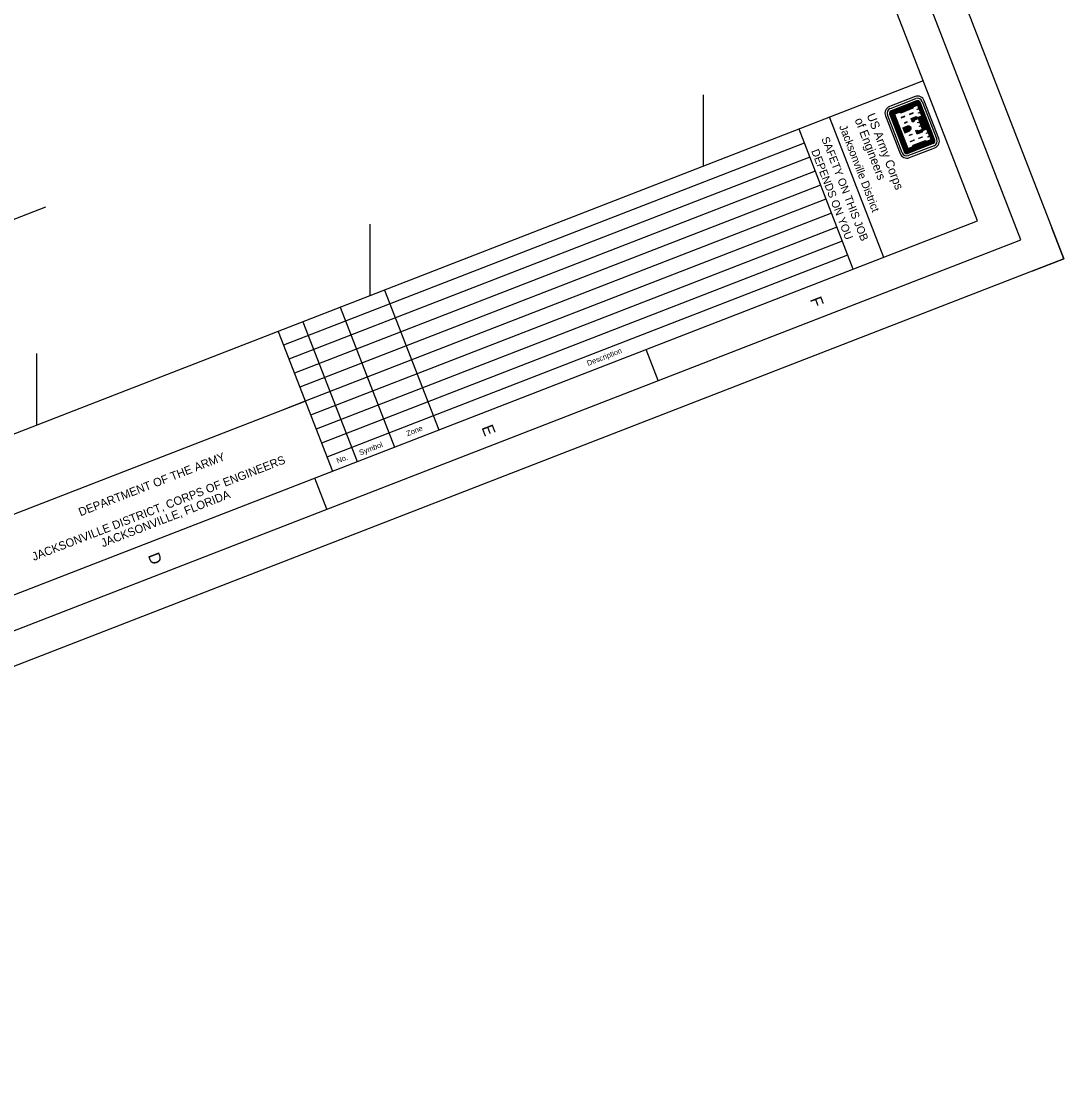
# Model space of a CAD drawing. Extents: x 587779 to 592541, y 824574 to 829906.
# Drawn here: x 590976 to 592541, y 824574 to 826161 of the extents above; entities that cross this region are included whole.
import ezdxf

# ---------------------------------------------------------------- set-up
doc = ezdxf.new("R2010")
doc.units = 0
for name, color, linetype in [('G-ANNO-NPLT', 7, 'Continuous'), ('G-ANNO-TEXT-LOGO', 7, 'Continuous'), ('G-ANNO-TEXT-TTLB', 7, 'Continuous'), ('G-ANNO-TTLB', 7, 'Continuous'), ('V-ANNO-MATC', 7, 'Continuous'), ('V-TOPO-COOR-STAT', 7, 'Continuous')]:
    doc.layers.add(name, color=color, linetype=linetype)

msp = doc.modelspace()

# ---------------------------------------------------------------- linework, layer by layer
at = {"layer": 'G-ANNO-NPLT'}
msp.add_lwpolyline([(590949.1, 829906.3), (592540.6, 825804.2), (589370.9, 824574.4), (587779.3, 828676.5)], close=True, dxfattribs=at)
msp.add_lwpolyline([(592494, 825786.1), (592540.6, 825804.2), (592522.5, 825850.8)], dxfattribs=at)
at = {"layer": 'G-ANNO-TEXT-LOGO'}
for p, q in [((592317.4, 826047.6), (592279.2, 826032.8)), ((592280.3, 826029.8), (592318.5, 826044.6)), ((592319.8, 826041.3), (592281.6, 826026.5)), ((592320.1, 826040.5), (592281.9, 826025.7)), ((592320.4, 826039.8), (592282.2, 826024.9)), ((592320.8, 826038.9), (592282.5, 826024.1)), ((592321.1, 826038.1), (592282.9, 826023.2)), ((592321.4, 826037.2), (592283.5, 826022.5)), ((592343.8, 825981.1), (592321.8, 826037.8)), ((592344.6, 825981.5), (592322.7, 826038.2)), ((592345.4, 825981.8), (592323.4, 826038.4)), ((592346.2, 825982.1), (592324.2, 826038.8)), ((592347.1, 825982.4), (592325.1, 826039.1)), ((592328.3, 826040.3), (592350.2, 825983.6)), ((592353.2, 825984.8), (592331.2, 826041.5)), ((592301.3, 825964.7), (592279.3, 826021.3)), ((592302, 825964.9), (592280.1, 826021.6)), ((592302.9, 825965.3), (592280.9, 826022)), ((592303.7, 825965.6), (592281.7, 826022.3)), ((592304.5, 825965.9), (592282.5, 826022.6)), ((592305.2, 825966.6), (592283.5, 826022.5)), ((592321.7, 826036.5), (592284.6, 826022.1)), ((592305.7, 825967.7), (592284.6, 826022.1)), ((592313.8, 826032.7), (592294.3, 826025.1)), ((592313.3, 826031.5), (592295.5, 826024.6)), ((592273, 826018.9), (592295, 825962.2)), ((592298, 825963.4), (592276, 826020.1)), ((592323.9, 826016), (592330.6, 825998.6)), ((592324.7, 826016.3), (592331.4, 825999)), ((592325.4, 826016.6), (592332.2, 825999.3)), ((592326.3, 826016.9), (592333, 825999.6)), ((592327.1, 826017.3), (592333.8, 825999.9)), ((592327.9, 826017.5), (592334.6, 826000.2)), ((592328.7, 826017.9), (592335.4, 826000.5)), ((592299.2, 826000.7), (592305.4, 826003.2)), ((592299.2, 826000.7), (592302.1, 825993.3)), ((592299.5, 826000), (592305.7, 826002.4)), ((592299.8, 825999.2), (592306.1, 826001.6)), ((592300.1, 825998.3), (592306.4, 826000.7)), ((592300.4, 825997.6), (592306.7, 826000)), ((592300.9, 825996.4), (592307.1, 825998.9)), ((592301.2, 825995.7), (592307.4, 825998.1)), ((592301.5, 825994.9), (592307.7, 825997.3)), ((592301.8, 825994), (592308.1, 825996.4)), ((592302.1, 825993.3), (592308.3, 825995.7)), ((592343.1, 825981.3), (592305.2, 825966.6)), ((592343.4, 825980.5), (592305.2, 825965.6)), ((592343.8, 825979.6), (592305.5, 825964.8)), ((592342.8, 825982), (592305.7, 825967.7)), ((592344, 825978.9), (592305.8, 825964)), ((592344.4, 825978), (592306.1, 825963.2)), ((592344.7, 825977.2), (592306.5, 825962.4)), ((592345.9, 825974), (592307.7, 825959.2)), ((592334.4, 825979.5), (592315, 825972)), ((592333.3, 825980.1), (592315.5, 825973.2)), ((592308.9, 825956.1), (592347.1, 825971))]:
    msp.add_line(p, q, dxfattribs=at)
for points in [[(592321.9, 826035.8), (592314.6, 826033), (592313.6, 826030.8), (592295.8, 826023.9), (592293.5, 826024.8), (592285.4, 826021.7), (592306, 825968.5), (592314.1, 825971.7), (592315.2, 825974), (592333, 825980.9), (592335.2, 825979.8), (592342.6, 825982.7), (592339.9, 825989.7), (592337.8, 825995.1), (592335.8, 826000.1), (592328.4, 825997.3), (592327.5, 825994.9), (592321, 825992.4), (592319.5, 825996.3), (592320.1, 825996.5), (592322.5, 825995.5), (592329.7, 825998.3), (592327, 826005.3), (592324.9, 826010.7), (592323, 826015.7), (592315.7, 826012.8), (592314.7, 826010.5), (592314.1, 826010.3), (592312.5, 826014.2), (592319.1, 826016.7), (592321.3, 826015.6), (592328.7, 826018.5), (592326, 826025.5), (592323.9, 826030.9), (592321.9, 826035.8)], [(592321.4, 826034.8), (592315.2, 826032.4), (592314.2, 826030.1), (592295.8, 826022.9), (592293.4, 826023.9), (592286.5, 826021.2), (592306.6, 825969.6), (592313.5, 825972.3), (592314.5, 825974.7), (592332.9, 825981.9), (592335.3, 825980.7), (592341.4, 825983.1), (592339.5, 825988.2), (592336.6, 825987), (592336.4, 825987.5), (592339.3, 825988.6), (592337.4, 825993.6), (592334.5, 825992.4), (592334.3, 825992.8), (592337.2, 825993.9), (592335.3, 825999), (592329.1, 825996.6), (592328.1, 825994.3), (592320.6, 825991.3), (592318.5, 825996.7), (592320.2, 825997.4), (592322.6, 825996.4), (592328.7, 825998.8), (592326.8, 826003.8), (592323.9, 826002.7), (592323.7, 826003.1), (592326.6, 826004.2), (592324.7, 826009.2), (592321.8, 826008.1), (592321.6, 826008.6), (592324.5, 826009.7), (592322.6, 826014.6), (592316.4, 826012.2), (592315.4, 826009.9), (592313.6, 826009.2), (592311.5, 826014.6), (592319.1, 826017.6), (592321.4, 826016.5), (592327.5, 826018.9), (592325.6, 826023.9), (592322.7, 826022.7), (592322.6, 826023.2), (592325.4, 826024.3), (592323.5, 826029.4), (592320.6, 826028.2), (592320.5, 826028.6), (592323.3, 826029.7), (592321.4, 826034.8)], [(592314.4, 826023.3), (592309, 826021.2), (592309.2, 826020.6), (592314.6, 826022.7), (592314.4, 826023.3)], [(592302, 826018.4), (592296.5, 826016.3), (592296.7, 826015.8), (592302.2, 826017.9), (592302, 826018.4)], [(592305.3, 826009.9), (592301.5, 826008.4), (592301.7, 826007.9), (592305.5, 826009.4), (592305.3, 826009.9)], [(592319.7, 826015.4), (592319, 826015.7), (592313.7, 826013.7), (592314.4, 826011.9), (592315.1, 826013.6), (592319.8, 826015.4)], [(592312.8, 825990.7), (592308.9, 825989.2), (592308.8, 825989.6), (592312.6, 825991.1), (592312.8, 825990.7)], [(592327.1, 825996.2), (592326.8, 825995.6), (592321.5, 825993.5), (592320.9, 825995.2), (592322.5, 825994.6), (592327.2, 825996.4)], [(592316.1, 825982.2), (592310.6, 825980), (592310.4, 825980.5), (592315.9, 825982.6), (592316.1, 825982.2)], [(592328.5, 825987), (592323, 825984.9), (592322.9, 825985.4), (592328.3, 825987.5), (592328.5, 825987)]]:
    msp.add_lwpolyline(points, dxfattribs=at)
for centre, major_axis, start_param, end_param in [((592321.3, 826037.6), (3.88, -9.99), 1.57078, 3.141576), ((592321.3, 826037.6), (2.71, -6.98), 1.57078, 3.141576), ((592321.3, 826037.6), (1.45, -3.75), 1.57078, 3.141576), ((592321.3, 826037.6), (1.14, -2.94), 1.57078, 3.141576), ((592321.3, 826037.6), (0.83, -2.13), 1.57078, 3.141576), ((592321.3, 826037.6), (0.51, -1.32), 1.57078, 3.141576), ((592321.3, 826037.6), (0.197, -0.509), 1.57078, 3.141576), ((592283, 826022.7), (-3.88, 9.99), 6.28317, 7.853966), ((592283, 826022.7), (-2.71, 6.98), 6.28317, 7.853966), ((592283, 826022.7), (-1.45, 3.75), 6.28317, 7.853966), ((592283, 826022.7), (-1.14, 2.94), 6.28317, 7.853966), ((592283, 826022.7), (-0.83, 2.13), 6.28317, 7.853966), ((592283, 826022.7), (-0.51, 1.32), 6.28317, 7.853966), ((592283, 826022.7), (-0.197, 0.509), 6.28317, 7.853966), ((592307, 825997.9), (-2.01, 5.18), 4.985832, 6.214359), ((592307, 825997.9), (-1.69, 4.37), 4.947465, 6.21436), ((592307, 825997.9), (-1.38, 3.56), 4.947465, 6.21436), ((592307, 825997.9), (-1.07, 2.75), 4.947465, 6.21436), ((592307, 825997.9), (-0.75, 1.94), 4.947465, 6.214359), ((592305.9, 826000.7), (0.75, -1.94), 0.068794, 1.335689), ((592305.9, 826000.7), (1.07, -2.75), 0.068794, 1.335689), ((592305.9, 826000.7), (1.38, -3.56), 0.068795, 1.335689), ((592305.9, 826000.7), (1.69, -4.37), 0.068795, 1.335689), ((592305.9, 826000.7), (2.01, -5.18), 0.068795, 1.29842), ((592343.2, 825981), (0.197, -0.509), 6.283169, 7.853965), ((592343.2, 825981), (0.51, -1.32), 6.283169, 7.853965), ((592343.2, 825981), (0.83, -2.13), 6.283169, 7.853965), ((592343.2, 825981), (1.14, -2.94), 6.283169, 7.853965), ((592343.2, 825981), (1.45, -3.75), 6.283169, 7.853965), ((592343.2, 825981), (2.71, -6.98), 6.28317, 7.853966), ((592343.2, 825981), (3.88, -9.99), 6.283169, 7.853965), ((592305, 825966.1), (3.88, -9.99), 4.712373, 6.28317), ((592305, 825966.1), (-2.71, 6.98), 1.570781, 3.141577), ((592305, 825966.1), (1.45, -3.75), 4.712373, 6.28317), ((592305, 825966.1), (1.14, -2.94), 4.712373, 6.28317), ((592305, 825966.1), (0.83, -2.13), 4.712373, 6.28317), ((592305, 825966.1), (0.51, -1.32), 4.712373, 6.28317), ((592305, 825966.1), (0.197, -0.509), 4.712373, 6.28317)]:
    msp.add_ellipse(centre, major_axis=major_axis, ratio=0.99964, start_param=start_param, end_param=end_param, dxfattribs=at)
at = {"layer": 'G-ANNO-TTLB'}
for p, q in [((592329.8, 826071.1), (589346.5, 824913.6)), ((592188.8, 826016.3), (592270.2, 825806.6)), ((592142.8, 825999.1), (592224.2, 825789.4)), ((592151.1, 825977.8), (591369.9, 825674.7)), ((592159.3, 825956.8), (591378.1, 825653.7)), ((592167.4, 825935.8), (591386.2, 825632.7)), ((592175.5, 825914.8), (591394.4, 825611.8)), ((592183.7, 825893.9), (591402.5, 825590.8)), ((592191.8, 825872.9), (591410.6, 825569.8)), ((592199.9, 825851.9), (591418.8, 825548.8)), ((592208.1, 825830.9), (591426.9, 825527.9)), ((592216.2, 825810), (591435, 825506.9)), ((591521.3, 825757.3), (591602.7, 825547.6)), ((591455, 825731.6), (591536.3, 825521.8)), ((591399, 825709.9), (591480.4, 825500.1)), ((591361.9, 825695.5), (591443.3, 825485.7)), ((591931.9, 825621.7), (591913.8, 825668.3)), ((590601, 825280.3), (591402.6, 825590.6)), ((591402.6, 825590.6), (591369.5, 825577.8)), ((591434.7, 825428.8), (591416.7, 825475.4))]:
    msp.add_line(p, q, dxfattribs=at)
for points in [[(587844, 828647.9), (589399.4, 824639.1), (592475.9, 825832.7), (590920.6, 829841.6)], [(592411.2, 825861.3), (590919.2, 829706.9), (587935.9, 828549.5), (589427.9, 824703.8)]]:
    msp.add_lwpolyline(points, close=True, dxfattribs=at)
at = {"layer": 'V-ANNO-MATC'}
msp.add_line((591012.7, 825881.8), (590445.6, 825661.8), dxfattribs=at)
at = {"layer": 'V-TOPO-COOR-STAT'}
for p, q in [((592000, 825943.1), (592000, 826050.4)), ((591500, 825749.1), (591500, 825856.4)), ((591000, 825555.1), (591000, 825662.4))]:
    msp.add_line(p, q, dxfattribs=at)

# ---------------------------------------------------------------- texts
at = {"layer": 'G-ANNO-TEXT-TTLB'}
for s, height, rotation, p in [('US Army Corps', 13.086, 291.2052, (592244.6, 826019.8)), ('of Engineers', 13.086, 291.2052, (592226.5, 826012.8)), ('Jacksonville District', 11.9, 291.2052, (592203.3, 826002.7)), ('SAFETY ON THIS JOB', 11.9, 291.2052, (592176.6, 825984.7)), ('DEPENDS ON YOU', 11.9, 291.2052, (592161.4, 825966.1)), ('Description', 8, 21.2052, (591826.9, 825643.6)), ('Zone', 8, 21.2052, (591556, 825538.1)), ('Symbol', 8, 21.2052, (591485.2, 825509.4)), ('DEPARTMENT OF THE ARMY', 12.5, 21.2052, (591065.3, 825418.1)), ('JACKSONVILLE DISTRICT, CORPS OF ENGINEERS', 12.5, 21.2052, (590995.4, 825351.2)), ('No.', 8, 21.2052, (591451.2, 825497.3)), ('JACKSONVILLE, FLORIDA', 12.5, 21.2052, (591098.9, 825371.6))]:
    msp.add_text(s, height=height, rotation=rotation, dxfattribs=at).set_placement(p)
at = {"layer": 'G-ANNO-TTLB'}
for s, p in [('F', (592159.5, 825743.5)), ('E', (591666.7, 825551.4)), ('D', (591166.1, 825359.6))]:
    msp.add_text(s, height=17.5, rotation=291.2052, dxfattribs=at).set_placement(p)

doc.saveas('drawing.dxf')
